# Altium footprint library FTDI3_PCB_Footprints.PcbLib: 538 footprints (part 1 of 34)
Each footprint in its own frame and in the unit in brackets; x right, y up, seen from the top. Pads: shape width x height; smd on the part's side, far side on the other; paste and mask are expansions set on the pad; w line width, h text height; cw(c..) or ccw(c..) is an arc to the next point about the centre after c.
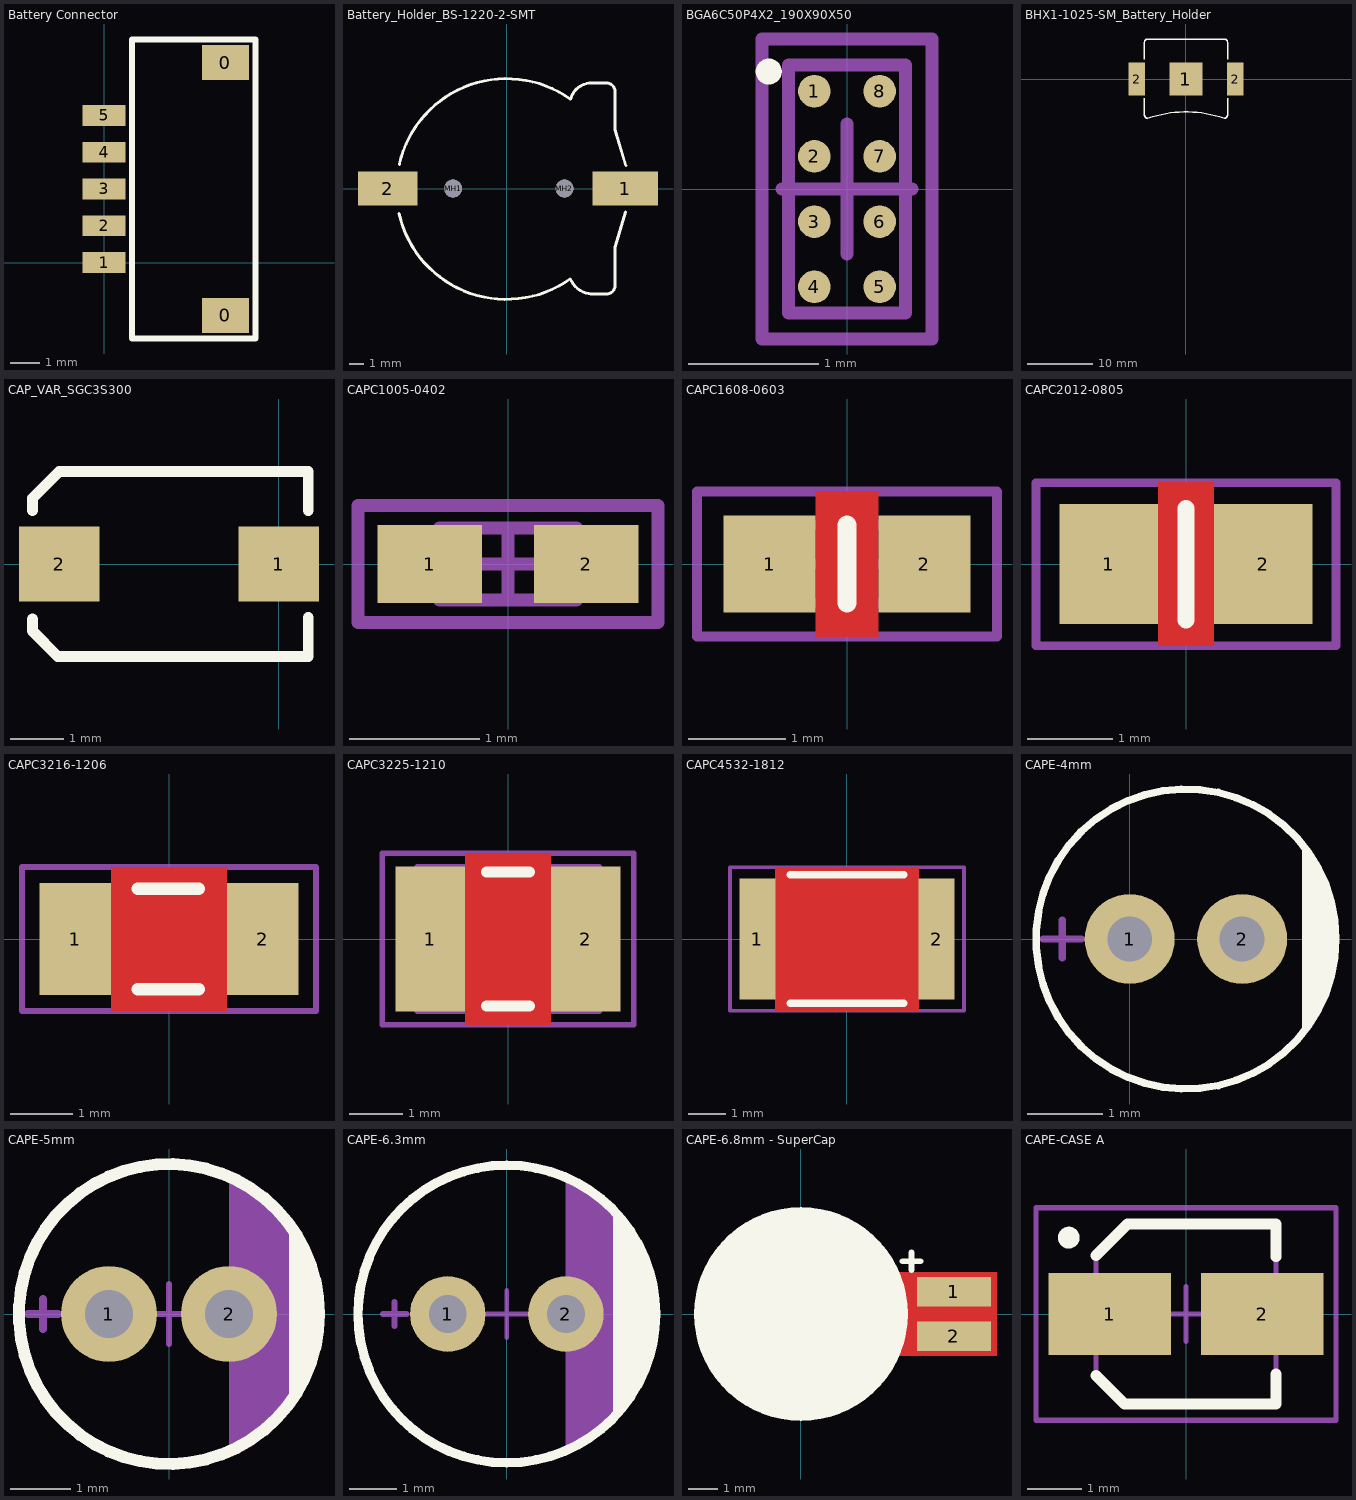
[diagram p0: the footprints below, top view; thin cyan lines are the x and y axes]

## Battery Connector [mm]
pads (7):
  rect 1.6x1.2 smd: 0(4.125,-1.8) 0(4.125,6.8)
  rect 1.45x0.7 smd: 1(0,0) 2(0,1.25) 3(0,2.5) 4(0,3.75) 5(0,5)
Top Overlay:
  lines w0.203: 0.95,-2.58 5.141,-2.58 5.141,7.58 0.95,7.58 0.95,-2.58

## Battery_Holder_BS-1220-2-SMT [mm] "Battery holder for CR1025; Memory Protection Devices"
height 3
pads (4):
  rect 4.4x2.3 smd: 1(8,0)
  rect 4x2.3 smd: 2(-8,0)
  round 1.2 hole 1.2 unplated: MH1(-3.6,0) MH2(3.9,0)
Top Overlay:
  lines w0.2: -7.235,-1.689 ccw(c-0.016,-0.062) 4.29,-6.08 ccw(c5.84,-5.42) 5.74,-7.102 ; -7.219,1.627 cw(c0,0) 4.306,6.018 cw(c5.729,5.627) 5.76,7.102 ; 5.64,-7.1 6.75,-7.1 ccw(c6.75,-6.55) 7.3,-6.55 ; 5.64,7.1 6.75,7.1 cw(c6.75,6.55) 7.3,6.55 ; 7.3,-6.64 7.3,-3.96 8.017,-1.587 ; 7.3,6.64 7.3,3.96 8.03,1.544
3D body: height 4, standoff 0, extent -7.431,-7.475 7.51,7.495

## BGA6C50P4X2_190X90X50 [mm] "BGA, 6-Leads, Body 1.9x0.9mm,  Pitch 0.50mm"
height 0.5
pads (8):
  round 0.25 smd mask+0.075: 1(-0.25,0.75) 2(-0.25,0.25) 3(-0.25,-0.25) 4(-0.25,-0.75) 5(0.25,-0.75) 6(0.25,-0.25) 7(0.25,0.25) 8(0.25,0.75)
Top Overlay:
  circle w0.1: c-0.6,0.9 r0.05
M13_Assembly_Info:
  lines w0.1: -0.45,-0.95 0.45,-0.95 0.45,0.95 -0.45,0.95 -0.45,-0.95
M15_Country_Yard:
  lines w0.1: -0.5,0 0.5,0 ; 0,-0.5 0,0.5 ; -0.65,-1.15 0.65,-1.15 0.65,1.15 -0.65,1.15 -0.65,-1.15
3D body: height 0.5, standoff 0.19, extent -0.45,-0.95 0.45,0.95

## BHX1-1025-SM_Battery_Holder [mm] "Battery holder for CR1025; Memory Protection Devices"
height 3
pads (3):
  rect 5x5 smd: 1(0,0)
  rect 2.5x5.1 smd: 2(-7.5,0) 2(7.5,0)
Top Overlay:
  lines w0.2: -6.35,-2.9 -6.35,-5.45 ccw(c-5.8,-5.45) -5.8,-6 cw(c0,-22.318) 5.8,-6 ; -6.35,3 -6.35,5.55 cw(c-5.8,5.55) -5.8,6.1 5.8,6.1 cw(c5.8,5.55) 6.35,5.55 6.35,3 ; 5.8,-6 ccw(c5.8,-5.45) 6.35,-5.45 6.35,-2.9

## CAP_VAR_SGC3S300 [mm] "MURATA TRIMMER CAP TZ03 SERIES - E TYPE"
height 4.8
pads (2):
  rect 1.5x1.4 smd: 1(0,0) 2(-4.1,0)
Top Overlay:
  lines w0.2: -4.6,-1.025 -4.6,-1.25 -4.125,-1.725 0.55,-1.725 0.55,-1 ; -4.6,1 -4.6,1.225 -4.1,1.725 0.55,1.725 0.55,1

## CAPC1005-0402 [mm] "Chip Capacitor, 2-Leads, Body 1.0x0.5mm, IPC Medium Density"
height 0.6
pads (2):
  rect 0.8x0.6 smd: 1(-0.6,0) 2(0.6,0)
M13_Assembly_Info:
  lines w0.1: -0.525,-0.275 0.525,-0.275 0.525,0.275 -0.525,0.275 -0.525,-0.275
M15_Country_Yard:
  lines w0.1: -0.275,0 0.275,0 ; 0,-0.275 0,0.275 ; -1.15,-0.45 1.15,-0.45 1.15,0.45 -1.15,0.45 -1.15,-0.45
3D body: height 0.6, standoff 0, extent -0.525,-0.275 0.525,0.275

## CAPC1608-0603 [mm] "Chip Capacitor; Body 1.6 x 0.8 mm (LxW typ)"
height 0.6
pads (2):
  rect 0.95x1 smd: 1(-0.8,0) 2(0.8,0)
Top Layer:
  pour cut-out: -0.325,0.75 0.325,0.75 0.325,-0.75 -0.325,-0.75
Top Overlay:
  lines w0.2: 0,-0.4 0,0.4
M13_Assembly_Info:
  lines w0.1: -0.8,-0.4 -0.8,0.4 0.8,0.4 0.8,-0.4 -0.8,-0.4
M15_Country_Yard:
  lines w0.1: -0.35,0 0.35,0 ; 0,-0.35 0,0.35 ; -1.55,-0.75 1.55,-0.75 1.55,0.75 -1.55,0.75 -1.55,-0.75
3D body: height 0.82, standoff 0.02, extent -0.8,-0.425 0.8,0.435

## CAPC2012-0805 [mm] "Chip Capacitor; Body 2 x 1.3 mm (LxW typ)"
height 0.65
pads (2):
  rect 1.15x1.4 smd: 1(-0.9,0) 2(0.9,0)
Top Layer:
  pour cut-out: -0.325,0.955 0.325,0.955 0.325,-0.95 -0.325,-0.95
Top Overlay:
  lines w0.2: 0,-0.65 0,0.65
M13_Assembly_Info:
  lines w0.1: -1,-0.625 1,-0.625 1,0.625 -1,0.625 -1,-0.625
M15_Country_Yard:
  lines w0.1: -0.35,0 0.35,0 ; 0,-0.35 0,0.35 ; -1.75,-0.95 -1.75,0.95 1.75,0.95 1.75,-0.95 -1.75,-0.95
3D body: height 1.26, standoff 0.01, extent -1,-0.625 1,0.625

## CAPC3216-1206 [mm] "Chip Capacitor; Body 3.2 x 1.6 mm (LxW typ)"
height 0.71
pads (2):
  rect 1.15x1.8 smd: 1(-1.5,0) 2(1.5,0)
Top Layer:
  pour cut-out: -0.925,1.15 0.925,1.15 0.925,-1.15 -0.925,-1.15
Top Overlay:
  lines w0.2: -0.5,-0.8 0.475,-0.8 ; -0.5,0.8 0.475,0.8
M13_Assembly_Info:
  lines w0.1: -1.6,-0.8 1.6,-0.8 1.6,0.8 -1.6,0.8 -1.6,-0.8
M15_Country_Yard:
  lines w0.1: -0.5,0 0.5,0 ; 0,-0.5 0,0.5 ; -2.35,-1.15 2.35,-1.15 2.35,1.15 -2.35,1.15 -2.35,-1.15
3D body: height 0.85, standoff 0, extent -1.6,-0.8 -1,0.8
3D body: height 0.85, standoff 0, extent 1,-0.8 1.6,0.8
3D body: height 0.85, standoff 0, extent -1,-0.8 1,0.8

## CAPC3225-1210 [mm] "Chip Capacitor, 2-Leads, Body 3.2x2.5mm, IPC Medium Density"
height 2.79
pads (2):
  rect 1.3x2.7 smd: 1(-1.45,0) 2(1.45,0)
Top Layer:
  pour cut-out: -0.8,1.6 0.8,1.6 0.8,-1.6 -0.8,-1.6
Top Overlay:
  lines w0.2: -0.4,-1.25 0.4,-1.25 ; -0.4,1.25 0.4,1.25
M13_Assembly_Info:
  lines w0.1: -1.7,-1.35 -1.7,1.35 1.7,1.35 1.7,-1.35 -1.7,-1.35
M15_Country_Yard:
  lines w0.1: -0.5,0 0.5,0 ; 0,-0.5 0,0.5 ; -2.35,-1.6 -2.35,1.6 2.35,1.6 2.35,-1.6 -2.35,-1.6
3D body: height 1.1, standoff 0, extent -1.1,-1.25 1.1,1.25
3D body: height 1.1, standoff 0, extent -1.6,-1.25 -1.1,1.25
3D body: height 1.1, standoff 0, extent 1.1,-1.25 1.6,1.25

## CAPC4532-1812 [mm] "Chip Capacitor, 2-Leads, Body 4.5x3.2mm, IPC Medium Density"
height 2.8
pads (2):
  rect 0.95x3.2 smd: 1(-2.375,0) 2(2.375,0)
Top Layer:
  pour cut-out: -1.9,1.9 1.9,1.9 1.9,-1.9 -1.9,-1.9
Top Overlay:
  lines w0.2: -1.5,-1.7 1.5,-1.7 ; -1.5,1.7 1.5,1.7
M13_Assembly_Info:
  lines w0.1: -2.45,-1.3 -2.45,1.3 2.45,1.3 2.45,-1.3 -2.45,-1.3
M15_Country_Yard:
  lines w0.1: -0.5,0 0.5,0 ; 0,-0.5 0,0.5 ; -3.1,-1.9 -3.1,1.9 3.1,1.9 3.1,-1.9 -3.1,-1.9
3D body: height 1.3, standoff 0, extent -1.65,-1.6 1.65,1.6
3D body: height 1.3, standoff 0, extent -2.15,-1.6 -1.65,1.6
3D body: height 1.3, standoff 0, extent 1.65,-1.6 2.15,1.6

## CAPE-4mm [mm] "Capacitor, aluminium electrolitytic; DIA 4mm; Pitch 1.5mm"
height 11
pads (2):
  round 1.2 hole 0.6: 1(0,0) 2(1.5,0)
Top Overlay:
  circle w0.1: c0.75,0 r2
  region: 2.3,1.25 2.3,-1.275 2.575,-0.925 2.7,-0.55 2.725,-0.35 2.75,0 2.725,0.425 2.575,0.875
M13_Assembly_Info:
  lines w0.1: -1.15,0 -0.65,0 ; -0.9,-0.25 -0.9,0.25
3D body: height 6, standoff 0, extent -1.25,-2 2.734,1.992

## CAPE-5mm [mm] "Capacitor, aluminium electrolitytic; DIA 5mm; Pitch 2mm"
pads (2):
  round 1.6 hole 0.8: 1(-1,0) 2(1,0)
Top Overlay:
  circle w0.2: c0,0 r2.5
  region: 2,1.475 2,-1.475 2.275,-1.075 2.4,-0.75 2.5,-0.375 2.5,0 2.475,0.45 2.35,0.925
M13_Assembly_Info:
  circle w0.1: c0,0 r2.5
  region: 1,2.275 1,-2.275 1.425,-2.05 1.825,-1.7 2.15,-1.25 2.375,-0.75 2.475,-0.275 2.475,0.2 2.375,0.675 2.25,1.125 2.025,1.475 1.75,1.775 1.375,2.075
  lines w0.127: -2.35,0 -1.85,0 ; -2.1,-0.25 -2.1,0.25
M15_Country_Yard:
  lines w0.1: -0.5,0 0.5,0 ; 0,-0.5 0,0.5
3D body: height 7.29, standoff -3.51, extent -2.525,-2.525 2.525,2.526

## CAPE-6.3mm [mm] "Capacitor, aluminium electrolitytic; DIA 6,3mm; Pitch 2.5mm"
pads (2):
  round 1.6 hole 0.8: 1(-1.25,0) 2(1.25,0)
Top Overlay:
  circle w0.2: c0,0 r3.15
  region: 2.25,2.2 2.25,-2.175 2.675,-1.65 2.925,-1.2 3.1,-0.625 3.2,0.025 3.075,0.9 2.75,1.55
M13_Assembly_Info:
  circle w0.1: c0,0 r3.15
  region: 1.25,2.9 1.25,-2.9 1.775,-2.6 2.25,-2.2 2.625,-1.725 2.9,-1.2 3.075,-0.65 3.15,-0.05 3.1,0.55 2.925,1.125 2.85,1.3 2.625,1.725 2.3,2.15 1.8,2.575
  lines w0.127: -2.625,0 -2.125,0 ; -2.375,-0.25 -2.375,0.25
M15_Country_Yard:
  lines w0.1: -0.5,0 0.5,0 ; 0,-0.5 0,0.5
3D body: height 7.29, standoff -3.25, extent -3.175,-3.176 3.175,3.175

## CAPE-6.8mm - SuperCap [mm] "Capacitor, SuperCap; DIA 6,8mm; Pitch 1.5mm"
height 7.3
pads (2):
  rect 2.5x1 smd: 1(5.15,0.75) 2(5.15,-0.75)
Top Layer:
  pour cut-out: -2.7,-2.25 -2.875,-2 -3.05,-1.725 -3.3,-1.2 -3.45,-0.6 -3.5,0 -3.425,0.725 -3.225,1.4 -2.9,1.975 -2.475,2.475 -2,2.875 -1.5,3.175 -0.75,3.425 0,3.5 0.725,3.425 1.45,3.2 2.075,2.825 2.6,2.375 3,1.775 3.23,1.4 6.6,1.4 6.6,-1.4 3.22,-1.4 3,-1.775 2.625,-2.35 2.025,-2.85 1.4,-3.225 0.7,-3.425 0,-3.5 -0.75,-3.4 -1.5,-3.175 -2.125,-2.775
Top Overlay:
  circle w0.2: c0,0 r3.5
  region: -3.15,1.5 -2.6,2.325 -1.875,2.975 -0.975,3.35 -0.025,3.5 0.9,3.4 1.875,2.975 2.675,2.3 3.125,1.5 3.375,0.85 3.5,0 3.375,-0.9 3.15,-1.5 2.575,-2.35 1.875,-2.975 0.975,-3.325 0,-3.5 -1.025,-3.3 -1.925,-2.925 -2.625,-2.275 -3.175,-1.5 -3.375,-0.875 -3.5,-0.025 -3.4,0.8
  lines w0.2: 3.425,1.775 4.025,1.775 ; 3.725,1.475 3.725,2.075
M13_Assembly_Info:
  circle w0.1: c0,0 r3.5
  lines w0.127: 3.475,1.775 3.975,1.775 ; 3.725,1.525 3.725,2.025
M15_Country_Yard:
  lines w0.1: -0.5,0 0.5,0 ; 0,-0.5 0,0.5

## CAPE-CASE A [mm] "Capacitor aluminium electrolitytic; SMT, Case A"
pads (2):
  rect 2.25x1.5 smd: 1(-1.4,0) 2(1.4,0)
Top Overlay:
  circle w0.2: c-2.15,1.4 r0.1
  lines w0.2: -1.65,-1.125 -1.125,-1.65 1.65,-1.65 1.65,-1.1 ; -1.65,1.075 -1.075,1.65 1.65,1.65 1.65,1.05
M13_Assembly_Info:
  lines w0.1: -1.65,-1.125 -1.125,-1.65 1.65,-1.65 1.65,1.65 -1.075,1.65 -1.65,1.075 -1.65,-1.125
M15_Country_Yard:
  lines w0.1: -0.5,0 0.5,0 ; 0,-0.5 0,0.5 ; -2.75,-1.95 2.75,-1.95 2.75,1.95 -2.75,1.95 -2.75,-1.95
3D body: height 5.4, standoff 0, extent -1.825,-1.65 1.775,1.65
